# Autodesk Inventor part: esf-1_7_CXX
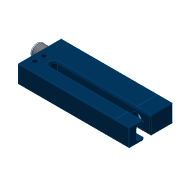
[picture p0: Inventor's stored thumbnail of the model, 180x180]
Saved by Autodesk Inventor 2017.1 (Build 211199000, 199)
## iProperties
Created: 2009-11
Part Number: esf-1_7_CXX
Document SubType Name: Modeling
Designer: Oliver Liedtke
Density: 1 g/cm^3
Material: Allgemein
Appearance: A Pantone 2945 U
Author: Oliver Liedtke
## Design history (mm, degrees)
sketch "Skizze1"
  geometry: L1 (-80.677, 27.769)-(19.323, 27.769); L2 (19.323, 27.769)-(19.323, 7.769); L3 (19.323, 7.769)-(-63.677, 7.769); L4 (-63.677, 1.769)-(19.323, 1.769); L5 (19.323, 1.769)-(19.323, -11.231); L6 (19.323, -11.231)-(-80.677, -11.231); L7 (-80.677, -11.231)-(-80.677, 27.769); A1 r 3 centre (-63.677, 4.769) between (-63.677, 7.769) and (-63.677, 1.769)
  constraints: 14 end point, 4 parallel, 2 perpendicular, 2 point on circle, 2 tangent, 1 centre point, 1 collinear, 1 horizontal
  dimensions: "d0" = 20 distance of L1.end L2.end; "d1" = 100 distance of L1.start L1.end; "d3" = 6 distance between parallel lines of L4 L3; "d128" = 13 distance of L4.end L5.end; "d461" = 17 distance from line of A1.centre L7
extrude "Gehäusekontur" new body sketch "Skizze1" distance "d9" = 16; taper "d10" = 0 deg
sketch "Skizze8"
  geometry: L1 (-80.677, -11.231)-(-80.677, 27.769) reference; A1 r 3 centre (-63.677, 4.769) between (-63.677, 7.769) and (-63.677, 1.769) reference; 3 further points
  dimensions: "d45" = 1.5 vertical distance of point (-74.677, 6.269) A1.centre; "d47" = 6.5 vertical distance of A1.centre point (-74.677, -1.731); "d48" = 7.5 vertical distance of point (-20.677, 12.269) A1.centre; "d49" = 6 distance from line of point (-74.677, -1.731) L1; "d50" = 6 distance from line of point (-74.677, 6.269) L1; "d52" = 60 distance from line of point (-20.677, 12.269) L1
hole "Befestigungsbohrungen" sketch "Skizze8" at (-74.677, 6.269), (-74.677, -1.731) diameter "d53" = 4.2; stored, may be unused: countersink angle "d57" = 90 deg, drill point angle "d59" = 118 deg; dims "d54" = 6, "d55" = 4, "d56" = 2, "d58" = 8
fillet "Rundung2" dims "d141" = 1.5
workplane "Arbeitsebene4"
  workplane "Arbeitsebene3"
sketch "Skizze25"
  geometry: L1 (1.5, 0)-(14.5, 0) reference; L2 (16, -80.535)-(16, 0.337) reference; C1 r 4.5 at (8, -13.5)
  constraints: 1 centre point
  dimensions: "d149" = 9 diameter of C1; "d150" = 13.5 distance from line of L1 C1.centre; "d151" = 8 distance from line of C1.centre L2
extrude "Bohrung USW" cut sketch "Skizze25" stored distance "d152" = 20; taper "d153" = 0 deg
workplane "Arbeitsebene5"
sketch "Skizze26"
  geometry: C1 r 4.5 at (8, -13.5) reference; C2 r 5.15 at (8, -13.5)
  constraints: 1 centre point, 1 coincident
  dimensions: "d155" = 10.3 diameter of C2
extrude "Stufe Sender USW" cut sketch "Skizze26" distance "d156" = 1; taper "d157" = 0 deg
workplane "Arbeitsebene6"
sketch "Skizze27"
  geometry: C1 r 4.5 at (8, -13.5) reference; C2 r 5.15 at (8, -13.5)
  constraints: 1 centre point, 1 coincident
  dimensions: "d159" = 10.3 diameter of C2
extrude "Stufe Empf. USW" cut sketch "Skizze27" distance "d160" = 2; taper "d161" = 0 deg
fillet "Rundung3" dims "d173" = 0.5
fillet "Rundung8" dims "d316" = 0.5
sketch "Skizze31"
  geometry: L1 (14.5, -0.487)-(14.5, -80.873) reference; L2 (1.5, -80.873)-(1.5, -0.487) reference; L3 (14, -25.5)-(2, -25.5); L4 (2, -25.5)-(2, 6.5); L5 (2, 6.5)-(14, 6.5); L6 (14, 6.5)-(14, -25.5); C1 r 4.5 at (8, -13.5) reference
  constraints: 8 end point, 2 parallel, 1 horizontal, 1 perpendicular
  dimensions: "d195" = 0.5 distance between parallel lines of L6 L1; "d196" = 0.5 distance between parallel lines of L2 L4; "d197" = 12 distance from line of C1.centre L3; "d198" = 20 distance from line of L5 C1.centre
extrude "V2: Schmutzrinne Sender #1" cut sketch "Skizze31" distance "d199" = 6.5; taper "d200" = 0 deg
sketch "Skizze32"
  geometry: L1 (0, 0)-(12, 0) reference; L2 (0, 0)-(0, -0.613) reference; L3 (12, -0.613)-(0, -0.613) reference; L4 (12, 0)-(12, -0.613) reference
extrude "V2: Schmutzrinne Sender #2" cut sketch "Skizze32" distance "d201" = 6.5; taper "d202" = 0 deg
fillet "V2: Rundung4" dims "d203" = 2
sketch "Skizze42"
  geometry: C1 r 4.5 at (0, 0) reference
extrude "Ex Empf." join sketch "Skizze42" distance "d314" = 5; taper "d315" = 0 deg
sketch "Skizze41"
  geometry: C1 r 4.5 at (0, 0) reference
extrude "Ex Sender" join sketch "Skizze41" distance "d312" = 5; taper "d313" = 0 deg
sketch "Skizze34" dims "d248" = 10, "d254" = 10
  geometry: L1 (14.278, -1.254)-(54.278, -1.254); L2 (54.278, -1.254)-(54.278, -6.979); L3 (54.278, -6.979)-(14.278, -6.979); L4 (14.278, -6.979)-(14.278, -1.254); L5 (22.23, -6.887)-(23.515, -6.887); L6 (24.333, -6.887)-(25.594, -6.887); L7 (26.426, -6.887)-(27.704, -6.887); L8 (22.23, -6.887)-(22.23, -4.326); L9 (23.515, -6.887)-(23.515, -4.493); L10 (24.333, -6.887)-(24.333, -4.493); L11 (25.594, -6.887)-(25.594, -4.493); L12 (26.426, -6.887)-(26.426, -4.493); L13 (27.704, -6.887)-(27.704, -4.326); L14 (28.081, -3.047)-(29.365, -3.047); L15 (29.365, -3.047)-(29.365, -6.887); L16 (29.365, -6.887)-(28.081, -6.887); L17 (28.081, -6.887)-(28.081, -3.047); L18 (31.384, -6.887)-(32.292, -6.887); L19 (32.292, -6.887)-(32.292, -5.726); L20 (32.292, -5.726)-(31.558, -5.726); L21 (31.547, -4.163)-(32.292, -4.163); L22 (32.292, -4.163)-(32.292, -2.969); L23 (32.292, -2.969)-(31.283, -2.969); L24 (32.685, -2.969)-(33.809, -2.969); L25 (33.809, -2.969)-(33.809, -3.665); L26 (32.685, -2.969)-(32.685, -6.887); L27 (32.685, -6.887)-(33.981, -6.887); L28 (33.981, -6.887)-(33.981, -4.79); L29 (34.651, -2.969)-(34.941, -2.969); L30 (34.941, -2.969)-(34.941, -4.171); L31 (34.941, -4.171)-(34.75, -4.171); L32 (54.342, -6.887)-(54.342, -5.726); L33 (53.434, -6.887)-(54.342, -6.887); L34 (54.342, -5.726)-(53.608, -5.726); L35 (51.415, -6.887)-(50.131, -6.887); L36 (50.131, -6.887)-(50.131, -3.047); L37 (51.415, -3.047)-(51.415, -6.887); L38 (50.131, -3.047)-(51.415, -3.047); L39 (53.597, -4.163)-(54.342, -4.163); L40 (54.342, -4.163)-(54.342, -2.969); L41 (54.342, -2.969)-(53.333, -2.969); L42 (39.262, -6.887)-(39.262, -5.813); L43 (39.262, -5.813)-(40.534, -5.813); L44 (39.262, -6.887)-(40.873, -6.887); L45 (40.76, -4.041)-(41.795, -4.041); L46 (41.795, -4.041)-(41.795, -2.969); L47 (41.795, -2.969)-(40.321, -2.969); L48 (46.421, -6.887)-(47.655, -6.887); L49 (47.655, -6.887)-(47.655, -4.545); L50 (46.421, -6.887)-(46.421, -4.545); L51 (48.528, -6.887)-(49.762, -6.887); L52 (49.762, -6.887)-(49.762, -4.545); L53 (48.528, -6.887)-(48.528, -4.545); L54 (21.019, -6.338)-(19.323, -1.511); L55 (20.444, -6.901)-(15.357, -6.901); L56 (21.019, -6.338)-(21.019, -1.251); L57 (21.019, -6.338)-(21.019, -1.251); L58 (20.747, -6.406)-(18.697, -1.749); L59 (20.747, -6.406)-(17.275, -2.666); L60 (20.444, -6.901)-(15.618, -5.215); L61 (18.913, -5.519)-(15.196, -2.071); L62 (18.913, -5.519)-(14.278, -3.498); C1 r 0.593 at (28.723, -2.236); C2 r 0.593 at (50.773, -2.236); A1 r 0.412 centre (23.924, -4.544) between (24.333, -4.493) and (23.515, -4.493); A2 r 0.42 centre (26.01, -4.551) between (26.426, -4.493) and (25.594, -4.493); A3 r 1.547 centre (23.771, -4.46) between (24.958, -3.468) and (22.23, -4.326); A4 r 1.559 centre (26.152, -4.47) between (27.704, -4.326) and (24.958, -3.468); A5 r 0.796 centre (31.702, -4.943) between (31.547, -4.163) and (31.558, -5.726); A6 r 1.98 centre (31.615, -4.921) between (31.283, -2.969) and (31.384, -6.887); A7 r 0.89 centre (34.677, -3.859) between (34.651, -2.969) and (33.809, -3.665); A8 r 0.722 centre (34.696, -4.891) between (34.75, -4.171) and (33.981, -4.79); A9 r 0.823 centre (37.038, -4.96) between (37.067, -4.137) and (37.073, -5.782); A10 r 0.823 centre (37.038, -4.96) between (37.073, -5.782) and (37.067, -4.137); A11 r 2.053 centre (37.038, -4.96) between (37.062, -2.907) and (37.078, -7.012); A12 r 2.053 centre (37.038, -4.96) between (37.078, -7.012) and (37.062, -2.907); A13 r 0.796 centre (53.752, -4.943) between (53.597, -4.163) and (53.608, -5.726); A14 r 1.98 centre (53.665, -4.921) between (53.333, -2.969) and (53.434, -6.887); A15 r 2.053 centre (44.188, -4.96) between (44.212, -2.907) and (44.228, -7.012); A16 r 2.053 centre (44.188, -4.96) between (44.228, -7.012) and (44.212, -2.907); A17 r 0.823 centre (44.188, -4.96) between (44.217, -4.137) and (44.223, -5.782); A18 r 0.823 centre (44.188, -4.96) between (44.223, -5.782) and (44.217, -4.137); A19 r 1.18 centre (40.472, -4.139) between (40.321, -2.969) and (39.911, -5.178); A20 r 0.177 centre (40.534, -5.636) between (40.534, -5.813) and (40.61, -5.476); A21 r 13.06 centre (45.381, 6.682) between (39.911, -5.178) and (40.61, -5.476); A22 r 1.153 centre (40.873, -5.734) between (40.873, -6.887) and (41.24, -4.641); A23 r 0.181 centre (40.737, -4.22) between (40.76, -4.041) and (40.648, -4.377); A24 r 7.424 centre (43.968, 2.263) between (40.648, -4.377) and (41.24, -4.641); A25 r 0.436 centre (48.091, -4.545) between (48.528, -4.545) and (47.655, -4.545); A26 r 1.671 centre (48.091, -4.545) between (49.762, -4.545) and (46.421, -4.545); A27 r 5.153 centre (19.011, -5.535) between (15.196, -2.071) and (14.278, -3.498); A28 r 5.661 centre (21.019, -6.913) between (15.618, -5.215) and (15.357, -6.901); A29 r 5.661 centre (21.019, -6.913) between (21.019, -1.251) and (19.323, -1.511); A30 r 5.661 centre (21.019, -6.913) between (18.697, -1.749) and (17.275, -2.666); 1 further point
  constraints: 116 end point, 61 point on circle, 32 centre point, 21 parallel, 15 perpendicular, 9 collinear, 6 concentric, 6 tangent, 4 horizontal, 4 point on line, 3 equal length, 1 vertical, 41 other
  dimensions: "d260" = 40 distance of L1.start L1.end; "d264" = 5.72525 distance of L3.end L1.start (derived); "d255" = 22.05 distance of L18.end L32.start; "d249" = 7.15 distance of A11.centre A15.centre
extrude "mic-Logo" cut sketch "Skizze34" taper "d262" = -10 deg; distance "d263" = 0.2
workplane "Arbeitsebene8"
  workplane "Arbeitsebene7"
sketch "Skizze39"
  geometry: L1 (18.823, -11.231)-(-80.177, -11.231) reference; L2 (-80.177, 27.769)-(18.823, 27.769) reference; L3 (2.703, 12.687)-(3.153, 14.636) reference; L4 (-80.177, -10.731)-(-80.177, 27.269) reference; L5 (18.823, 0.269)-(18.823, -10.731) reference; L6 (-63.677, 0.269)-(18.823, 0.269) reference; L7 (18.823, 9.269)-(-63.677, 9.269) reference; L8 (18.823, 27.269)-(18.823, 9.269) reference; L9 (12.739, 10.37)-(13.189, 12.319) reference; L10 (-0.419, -0.837)-(-0.644, -1.812) reference; L11 (9.617, -3.154)-(9.392, -4.129) reference; L12 (2.703, 12.687)-(12.739, 10.37) reference; L13 (-0.419, -0.837)-(9.617, -3.154) reference; L14 (7.721, 11.529)-(4.599, -1.996); L15 (6.16, 4.766)-(6.16, 18.813); L16 (6.16, 4.766)-(6.16, -8.181); L17 (5.86, 26.269)-(6.46, 26.269); L18 (6.46, 26.269)-(6.46, -9.731); L19 (6.46, -9.731)-(5.86, -9.731); L20 (5.86, -9.731)-(5.86, 26.269); L21 (-80.177, 27.269)-(18.823, 27.269) reference; L22 (18.823, -10.731)-(-80.177, -10.731) reference; C1 r 2.1 at (-74.677, 6.269) reference; C2 r 2.1 at (-74.677, -1.731) reference; A1 r 4.5 centre (-63.677, 4.769) between (-63.677, 9.269) and (-63.677, 0.269) reference
  constraints: 14 end point, 3 midpoint, 2 parallel, 1 collinear, 1 horizontal, 1 perpendicular
  dimensions: "d298" = 0.3 distance between parallel lines of L15 L20; "d299" = 0.3 distance between parallel lines of L16 L18; "d300" = 1.5 distance between parallel lines of L2 L17; "d301" = 1.5 distance between parallel lines of L19 L1
extrude "Marke rechts" cut sketch "Skizze39" distance "d302" = 0.2; taper "d303" = 0 deg
sketch "Skizze40"
  geometry: L1 (-6.46, 8.52)-(-6.46, 26.269) reference; L2 (-5.86, 26.269)-(-5.86, 8.52) reference; L3 (-6.46, 26.269)-(-5.86, 26.269) reference; L4 (-5.86, 26.269)-(-5.86, -9.731) reference; L5 (-6.46, -9.731)-(-6.46, 26.269) reference; L6 (-5.86, -9.731)-(-6.46, -9.731) reference; L7 (-6.46, 26.269)-(-5.86, 26.269); L8 (-5.86, 26.269)-(-5.86, -9.731); L9 (-5.86, -9.731)-(-6.46, -9.731); L10 (-6.46, -9.731)-(-6.46, 26.269); 3 further points
  constraints: 8 end point, 2 parallel, 1 horizontal, 1 perpendicular
extrude "Marke links" cut sketch "Skizze40" distance "d304" = 0.2; taper "d305" = 0 deg
sketch "Skizze43"
  geometry: L1 (15, 38.5)-(0, 38.5) reference; L2 (15.5, 0)-(15.5, 38) reference; C1 r 6 at (7.5, 26.5)
  constraints: 1 centre point
  dimensions: "d318" = 12 distance from line of C1.centre L1; "d319" = 8 distance from line of L2 C1.centre; "d320" = 12 diameter of C1
extrude "M12" join sketch "Skizze43" distance "d321" = 9; taper "d322" = 0 deg
sketch "Skizze44"
  geometry: C1 r 6 at (0, 0) reference; C2 r 5.25 at (0, 0)
  constraints: 1 centre point, 1 coincident
  dimensions: "d323" = 10.5 diameter of C2
extrude "Extrusion37" join sketch "Skizze44" distance "d324" = 1; taper "d325" = 0 deg
chamfer "Fase3" distance "d326" = 0.75; stored, may be unused: second distance "d327" = 2, angle "d328" = 45 deg
feature "Gewinde1" dims "d329" = 10, "d330" = 0
sketch "Skizze45"
  geometry: C1 r 5.25 at (0, 0) reference; C2 r 4.25 at (0, 0)
  constraints: 1 centre point, 1 coincident
  dimensions: "d331" = 8.5 diameter of C2
extrude "Extrusion38" cut sketch "Skizze45" distance "d332" = 9; taper "d333" = 0 deg
workplane "Arbeitsebene9"
sketch "Skizze46"
  geometry: L1 (0, 0)-(3.062, 2.947); L2 (0, 0)-(4.249, -0.081); L3 (3.447, 2.485)-(2.974, 2.03); L4 (2.615, 3.35)-(2.142, 2.894); A1 r 4.25 centre (0, 0) between (3.062, 2.947) and (4.249, -0.081) reference; A2 r 4.25 centre (0, 0) between (3.062, 2.947) and (4.249, -0.081) reference; A3 r 0.6 centre (2.558, 2.462) between (2.974, 2.03) and (2.142, 2.894); A4 r 4.25 centre (0, 0) between (3.447, 2.485) and (2.615, 3.35)
  constraints: 13 point on circle, 8 end point, 2 centre point, 2 parallel, 1 coincident, 1 point on line, 1 tangent
  dimensions: "d335" = 45 deg angle of L1 L2; "d336" = 0.6 distance between parallel lines of L1 L4; "d337" = 0.6 distance between parallel lines of L3 L1; "d338" = 0.7 distance of L1.end A3.centre
extrude "Extrusion39" join sketch "Skizze46" stored distance "d339" = 9; taper "d340" = 0 deg
sketch "Skizze48"
  geometry: C1 r 0.5 at (0, 0); C2 r 0.5 at (0, 2.5); C3 r 0.5 at (-2.5, 0); C4 r 0.5 at (0, -2.5); C5 r 0.5 at (2.5, 0); A1 r 4.25 centre (0, 0) between (2.615, 3.35) and (3.447, 2.485) reference
  constraints: 5 centre point, 1 coincident, 1 equal radius, 9 other
  dimensions: "d344" = 1 diameter of C1; "d345" = 2.5 distance of C2.centre A1.centre; "d348" = 360 deg dimension on A1.centre C2.centre (derived)
extrude "Extrusion40" join sketch "Skizze48" distance "d350" = 7; taper "d351" = 0 deg
fillet "Rundung9" dims "d352" = 0.5
sketch "Skizze49"
  geometry: L1 (53.5, 14.5)-(94.5, 14.5); L2 (96.5, 12.5)-(96.5, 2.5); L3 (94.5, 0.5)-(53.5, 0.5); L4 (51.5, 2.5)-(51.5, 12.5); L5 (99, 15.5)-(0, 15.5) reference; L6 (0, -0.5)-(99, -0.5) reference; L7 (99.5, 0)-(99.5, 15) reference; A1 r 2 centre (53.5, 2.5) between (51.5, 2.5) and (53.5, 0.5); A2 r 2 centre (53.5, 12.5) between (53.5, 14.5) and (51.5, 12.5); A3 r 2 centre (94.5, 12.5) between (96.5, 12.5) and (94.5, 14.5); A4 r 2 centre (94.5, 2.5) between (94.5, 0.5) and (96.5, 2.5)
  constraints: 8 end point, 8 point on circle, 8 tangent, 4 centre point, 3 equal radius, 2 parallel, 1 horizontal, 1 perpendicular
  dimensions: "d353" = 1 distance between parallel lines of L1 L5; "d354" = 1 distance between parallel lines of L6 L3; "d355" = 3 distance between parallel lines of L7 L2; "d356" = 45 distance between parallel lines of L2 L4; "d357" = 2 radius of A1
extrude "Extrusion41" join sketch "Skizze49" distance "d358" = 0.2; taper "d359" = 0 deg
sketch "Skizze50"
  geometry: L1 (96.5, 12.5)-(96.5, 2.5) reference; L2 (78.4, 12)-(80.3, 12); L3 (80.6, 11.7)-(80.6, 10.3); L4 (80.3, 10)-(78.4, 10); L5 (78.1, 10.3)-(78.1, 11.7); L6 (78.4, 8.5)-(80.3, 8.5); L7 (80.6, 8.2)-(80.6, 6.8); L8 (80.3, 6.5)-(78.4, 6.5); L9 (78.1, 6.8)-(78.1, 8.2); L10 (78.4, 5)-(80.3, 5); L11 (80.6, 4.7)-(80.6, 3.3); L12 (80.3, 3)-(78.4, 3); L13 (78.1, 3.3)-(78.1, 4.7); L14 (0, -0.5)-(99, -0.5) reference; C1 r 5 at (88.5, 7.5); A1 r 0.3 centre (78.4, 3.3) between (78.1, 3.3) and (78.4, 3); A2 r 0.3 centre (78.4, 4.7) between (78.4, 5) and (78.1, 4.7); A3 r 0.3 centre (80.3, 4.7) between (80.6, 4.7) and (80.3, 5); A4 r 0.3 centre (80.3, 3.3) between (80.3, 3) and (80.6, 3.3); A5 r 0.3 centre (80.3, 6.8) between (80.3, 6.5) and (80.6, 6.8); A6 r 0.3 centre (80.3, 8.2) between (80.6, 8.2) and (80.3, 8.5); A7 r 0.3 centre (78.4, 8.2) between (78.4, 8.5) and (78.1, 8.2); A8 r 0.3 centre (78.4, 6.8) between (78.1, 6.8) and (78.4, 6.5); A9 r 0.3 centre (78.4, 10.3) between (78.1, 10.3) and (78.4, 10); A10 r 0.3 centre (78.4, 11.7) between (78.4, 12) and (78.1, 11.7); A11 r 0.3 centre (80.3, 11.7) between (80.6, 11.7) and (80.3, 12); A12 r 0.3 centre (80.3, 10.3) between (80.3, 10) and (80.6, 10.3); 3 further points
  constraints: 24 end point, 24 point on circle, 24 tangent, 13 centre point, 11 equal radius, 6 parallel, 6 point on line, 4 equal length, 3 horizontal, 3 perpendicular, 2 collinear
  dimensions: "d360" = 10 diameter of C1; "d361" = 2.5 distance of point (80.6, 3) point (78.1, 3); "d362" = 2 distance of point (78.1, 3) point (78.1, 5); "d363" = 0.3 radius of A1; "d364" = 8 distance from line of C1.centre L1; "d365" = 15.9 distance between parallel lines of L3 L1; "d366" = 1.5 distance between parallel lines of L8 L10; "d367" = 1.5 distance between parallel lines of L4 L6; "d368" = 7 distance between parallel lines of L8 L14; "d369" = 8 distance from line of C1.centre L14
extrude "Extrusion42" join sketch "Skizze50" distance "d370" = 0.3; taper "d371" = 0 deg
fillet "Rundung10" dims "d372" = 0.3, "d373" = 5
sketch "Skizze51"
  geometry: 1 further point
  constraints: 1 other
feature "Prägen1" sketch "Skizze51" dims "d0" = 20, "d1" = 100, "d3" = 6, "d128" = 13, "d374" = 0.1, "d375" = 0, "d461" = 17
sketch "Skizze53" dims "d416" = 10, "d422" = 10
  geometry: L1 (17.046, 18.254)-(37.006, 18.254); L2 (37.006, 18.254)-(37.006, 15.397); L3 (37.006, 15.397)-(17.046, 15.397); L4 (17.046, 15.397)-(17.046, 18.254); L5 (21.014, 15.443)-(21.655, 15.443); L6 (22.064, 15.443)-(22.693, 15.443); L7 (23.108, 15.443)-(23.746, 15.443); L8 (21.014, 15.443)-(21.014, 16.721); L9 (21.655, 15.443)-(21.655, 16.637); L10 (22.064, 15.443)-(22.064, 16.637); L11 (22.693, 15.443)-(22.693, 16.637); L12 (23.108, 15.443)-(23.108, 16.637); L13 (23.746, 15.443)-(23.746, 16.721); L14 (23.934, 17.359)-(24.575, 17.359); L15 (24.575, 17.359)-(24.575, 15.443); L16 (24.575, 15.443)-(23.934, 15.443); L17 (23.934, 15.443)-(23.934, 17.359); L18 (25.582, 15.443)-(26.035, 15.443); L19 (26.035, 15.443)-(26.035, 16.023); L20 (26.035, 16.023)-(25.669, 16.023); L21 (25.663, 16.803)-(26.035, 16.803); L22 (26.035, 16.803)-(26.035, 17.398); L23 (26.035, 17.398)-(25.532, 17.398); L24 (26.231, 17.398)-(26.792, 17.398); L25 (26.792, 17.398)-(26.792, 17.051); L26 (26.231, 17.398)-(26.231, 15.443); L27 (26.231, 15.443)-(26.878, 15.443); L28 (26.878, 15.443)-(26.878, 16.489); L29 (27.212, 17.398)-(27.357, 17.398); L30 (27.357, 17.398)-(27.357, 16.798); L31 (27.357, 16.798)-(27.262, 16.798); L32 (37.038, 15.443)-(37.038, 16.023); L33 (36.585, 15.443)-(37.038, 15.443); L34 (37.038, 16.023)-(36.672, 16.023); L35 (35.578, 15.443)-(34.937, 15.443); L36 (34.937, 15.443)-(34.937, 17.359); L37 (35.578, 17.359)-(35.578, 15.443); L38 (34.937, 17.359)-(35.578, 17.359); L39 (36.666, 16.803)-(37.038, 16.803); L40 (37.038, 16.803)-(37.038, 17.398); L41 (37.038, 17.398)-(36.535, 17.398); L42 (29.513, 15.443)-(29.513, 15.979); L43 (29.513, 15.979)-(30.148, 15.979); L44 (29.513, 15.443)-(30.317, 15.443); L45 (30.261, 16.863)-(30.777, 16.863); L46 (30.777, 16.863)-(30.777, 17.398); L47 (30.777, 17.398)-(30.042, 17.398); L48 (33.085, 15.443)-(33.701, 15.443); L49 (33.701, 15.443)-(33.701, 16.612); L50 (33.085, 15.443)-(33.085, 16.612); L51 (34.137, 15.443)-(34.753, 15.443); L52 (34.753, 15.443)-(34.753, 16.612); L53 (34.137, 15.443)-(34.137, 16.612); L54 (20.41, 15.717)-(19.563, 18.125); L55 (20.123, 15.436)-(17.585, 15.436); L56 (20.41, 15.717)-(20.41, 18.255); L57 (20.41, 15.717)-(20.41, 18.255); L58 (20.274, 15.683)-(19.251, 18.007); L59 (20.274, 15.683)-(18.542, 17.55); L60 (20.123, 15.436)-(17.715, 16.278); L61 (19.359, 16.126)-(17.504, 17.846); L62 (19.359, 16.126)-(17.046, 17.134); C1 r 0.296 at (24.254, 17.764); C2 r 0.296 at (35.257, 17.764); A1 r 0.206 centre (21.859, 16.612) between (22.064, 16.637) and (21.655, 16.637); A2 r 0.209 centre (22.901, 16.609) between (23.108, 16.637) and (22.693, 16.637); A3 r 0.772 centre (21.783, 16.654) between (22.375, 17.149) and (21.014, 16.721); A4 r 0.778 centre (22.971, 16.649) between (23.746, 16.721) and (22.375, 17.149); A5 r 0.397 centre (25.741, 16.413) between (25.663, 16.803) and (25.669, 16.023); A6 r 0.988 centre (25.697, 16.424) between (25.532, 17.398) and (25.582, 15.443); A7 r 0.444 centre (27.225, 16.954) between (27.212, 17.398) and (26.792, 17.051); A8 r 0.36 centre (27.235, 16.439) between (27.262, 16.798) and (26.878, 16.489); A9 r 0.411 centre (28.403, 16.405) between (28.418, 16.815) and (28.421, 15.995); A10 r 0.411 centre (28.403, 16.405) between (28.421, 15.995) and (28.418, 16.815); A11 r 1.024 centre (28.403, 16.405) between (28.415, 17.429) and (28.423, 15.381); A12 r 1.024 centre (28.403, 16.405) between (28.423, 15.381) and (28.415, 17.429); A13 r 0.397 centre (36.744, 16.413) between (36.666, 16.803) and (36.672, 16.023); A14 r 0.988 centre (36.7, 16.424) between (36.535, 17.398) and (36.585, 15.443); A15 r 1.024 centre (31.971, 16.405) between (31.983, 17.429) and (31.991, 15.381); A16 r 1.024 centre (31.971, 16.405) between (31.991, 15.381) and (31.983, 17.429); A17 r 0.411 centre (31.971, 16.405) between (31.986, 16.815) and (31.989, 15.995); A18 r 0.411 centre (31.971, 16.405) between (31.989, 15.995) and (31.986, 16.815); A19 r 0.589 centre (30.117, 16.814) between (30.042, 17.398) and (29.837, 16.296); A20 r 0.088 centre (30.148, 16.067) between (30.148, 15.979) and (30.186, 16.147); A21 r 6.517 centre (32.566, 22.214) between (29.837, 16.296) and (30.186, 16.147); A22 r 0.575 centre (30.317, 16.018) between (30.317, 15.443) and (30.5, 16.564); A23 r 0.09 centre (30.249, 16.774) between (30.261, 16.863) and (30.205, 16.696); A24 r 3.704 centre (31.861, 20.009) between (30.205, 16.696) and (30.5, 16.564); A25 r 0.218 centre (33.919, 16.612) between (34.137, 16.612) and (33.701, 16.612); A26 r 0.834 centre (33.919, 16.612) between (34.753, 16.612) and (33.085, 16.612); A27 r 2.571 centre (19.408, 16.118) between (17.504, 17.846) and (17.046, 17.134); A28 r 2.825 centre (20.41, 15.43) between (17.715, 16.278) and (17.585, 15.436); A29 r 2.825 centre (20.41, 15.43) between (20.41, 18.255) and (19.563, 18.125); A30 r 2.825 centre (20.41, 15.43) between (19.251, 18.007) and (18.542, 17.55); 1 further point
  constraints: 116 end point, 61 point on circle, 32 centre point, 21 parallel, 15 perpendicular, 9 collinear, 6 concentric, 6 tangent, 4 horizontal, 4 point on line, 3 equal length, 1 vertical, 41 other
  dimensions: "d428" = 19.96 distance of L1.start L1.end; "d432" = 2.8569 distance of L3.end L1.start (derived); "d423" = 11.00295 distance of L18.end L32.start; "d417" = 3.56785 distance of A11.centre A15.centre
extrude "mic-Logo Folie" cut sketch "Skizze53" taper "d430" = -10 deg; distance "d431" = 0.1
sketch "Skizze54"
  geometry: L1 (73.512, 8.46)-(73.512, 7.218); L2 (72.726, 7.218)-(72.726, 8.46); L3 (72.726, 8.46)-(72.181, 8.46); L4 (72.181, 8.46)-(72.181, 7.218); L5 (71.615, 8.46)-(71.615, 6.356); L6 (71.615, 6.356)-(71.07, 6.356); L7 (71.07, 8.46)-(71.615, 8.46); L8 (71.07, 6.356)-(71.07, 8.46); L9 (69.026, 6.882)-(69.026, 6.356); L10 (69.026, 6.356)-(69.538, 6.356); L11 (69.503, 6.882)-(69.026, 6.882); L12 (69.026, 8.46)-(69.026, 7.931); L13 (69.026, 7.931)-(69.503, 7.931); L14 (69.026, 8.46)-(69.538, 8.46); L15 (68.453, 7.225)-(68.453, 8.46); L16 (67.908, 8.46)-(67.908, 7.218); L17 (68.453, 8.46)-(67.908, 8.46); L18 (67.342, 6.822)-(67.342, 6.316); L19 (74.057, 8.46)-(73.512, 8.46); L20 (74.057, 7.218)-(74.057, 8.46); L21 (74.849, 8.46)-(74.849, 7.218); L22 (75.394, 8.46)-(75.394, 7.218); L23 (75.394, 8.46)-(74.849, 8.46); L24 (55.359, 6.356)-(55.871, 6.356); L25 (55.359, 6.882)-(55.359, 6.356); L26 (55.836, 6.882)-(55.359, 6.882); L27 (55.359, 7.931)-(55.836, 7.931); L28 (55.359, 8.46)-(55.871, 8.46); L29 (55.359, 8.46)-(55.359, 7.931); L30 (64.655, 7.931)-(64.655, 8.46); L31 (64.655, 7.931)-(64.527, 7.931); L32 (64.218, 7.638)-(64.192, 7.123); L33 (63.674, 7.677)-(63.65, 7.207); L34 (63.214, 6.353)-(63.214, 6.884); L35 (63.214, 6.353)-(63.382, 6.353); L36 (63.214, 6.884)-(63.31, 6.884); L37 (57.936, 6.356)-(57.391, 6.356); L38 (57.391, 6.356)-(57.391, 8.46); L39 (57.391, 8.46)-(57.936, 8.46); L40 (57.936, 8.46)-(57.936, 6.356); L41 (58.485, 8.46)-(58.485, 7.237); L42 (59.03, 8.46)-(58.485, 8.46); L43 (59.03, 8.46)-(59.03, 7.237); L44 (59.832, 8.46)-(59.832, 7.237); L45 (60.377, 8.46)-(59.832, 8.46); L46 (60.377, 8.46)-(60.377, 7.237); L47 (76.273, 8.801)-(54.315, 8.801); A1 r 0.393 centre (73.119, 7.218) between (72.726, 7.218) and (73.512, 7.218); A2 r 0.924 centre (73.105, 7.218) between (72.181, 7.218) and (73.787, 6.594); A3 r 1.052 centre (69.538, 7.408) between (69.538, 6.356) and (69.538, 8.46); A4 r 0.525 centre (69.503, 7.407) between (69.503, 6.882) and (69.503, 7.931); A5 r 0.927 centre (67.525, 7.225) between (67.342, 6.316) and (68.453, 7.225); A6 r 0.435 centre (67.473, 7.236) between (67.342, 6.822) and (67.908, 7.218); A7 r 0.396 centre (74.453, 7.218) between (74.057, 7.218) and (74.849, 7.218); A8 r 0.924 centre (74.47, 7.218) between (73.787, 6.594) and (75.394, 7.218); A9 r 1.052 centre (55.871, 7.408) between (55.871, 6.356) and (55.871, 8.46); A10 r 0.525 centre (55.836, 7.407) between (55.836, 6.882) and (55.836, 7.931); A11 r 1.337 centre (64.543, 7.128) between (64.655, 8.46) and (64.276, 8.438); A12 r 0.836 centre (64.508, 7.635) between (64.276, 8.438) and (63.674, 7.677); A13 r 0.811 centre (63.382, 7.164) between (63.382, 6.353) and (64.192, 7.123); A14 r 0.34 centre (63.31, 7.224) between (63.31, 6.884) and (63.65, 7.207); A15 r 0.309 centre (64.527, 7.622) between (64.527, 7.931) and (64.218, 7.638); A16 r 0.401 centre (59.431, 7.237) between (59.03, 7.237) and (59.832, 7.237); A17 r 0.946 centre (59.431, 7.237) between (58.485, 7.237) and (60.377, 7.237); 8 further points; 4 other entities
  constraints: 94 end point, 34 point on circle, 27 parallel, 24 tangent, 17 centre point, 12 perpendicular, 10 equal length, 9 collinear, 3 vertical, 2 coincident, 2 horizontal, 1 concentric, 1 equal radius, 8 other
  dimensions: "d445" = 0.545 distance of L22.start L21.start; "d446" = 0.79221 distance between parallel lines of L20 L21; "d447" = 0.78588 distance between parallel lines of L2 L1; "d448" = 1.24215 distance of L21.start L21.end; "d449" = 0.54503 distance of L7.start L5.start; "d450" = 0.54502 distance of L15.end L16.start; "d451" = 0.54502 distance of L45.start L44.start; "d452" = 20.03453 distance between parallel lines of L25 L22
extrude "mic-Logo-Folie_neu" join sketch "Skizze54" distance "d459" = 0.05; taper "d460" = 0 deg
node "Volumenkörper1"
node "Volumenkörper"
node "Flächenkörper"
node "Projizierte Kontur5"
node "Projizierte Kontur6"
other parameters: "d79" = 1, "d110" = 4, "d143" = 3, "d144" = -13 deg, "d154" = -6.98, "d158" = 6.9, "d288" = 90 deg, "d289" = 2, "d334" = -1
